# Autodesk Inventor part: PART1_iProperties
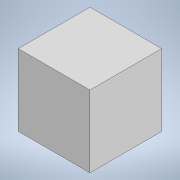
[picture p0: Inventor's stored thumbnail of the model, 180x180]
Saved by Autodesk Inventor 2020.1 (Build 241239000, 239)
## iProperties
Created: 2019-11
Part Number: PART1_iProperties
Material: Generic
Document SubType Name: Modeling
Designer: Synergysoft Dell02
Density: 1 g/cm^3
Appearance: Default
Author: Synergysoft Dell02
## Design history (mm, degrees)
sketch "Sketch1"
  geometry: L1 (25, 25)-(-25, 25); L2 (-25, 25)-(-25, -25); L3 (-25, -25)-(25, -25); L4 (25, -25)-(25, 25); L5 (25, 25)-(-25, -25); L6 (-25, 25)-(25, -25); 1 further point
  constraints: 12 end point, 2 midpoint, 2 parallel, 1 horizontal, 1 perpendicular
  dimensions: "d0" = 50 distance of L3.end L2.end; "d1" = 50 distance of L2.end L1.end
extrude "Extrusion1" new body sketch "Sketch1" distance "d2" = 50; taper "d3" = 0 deg
body "Solid1"
